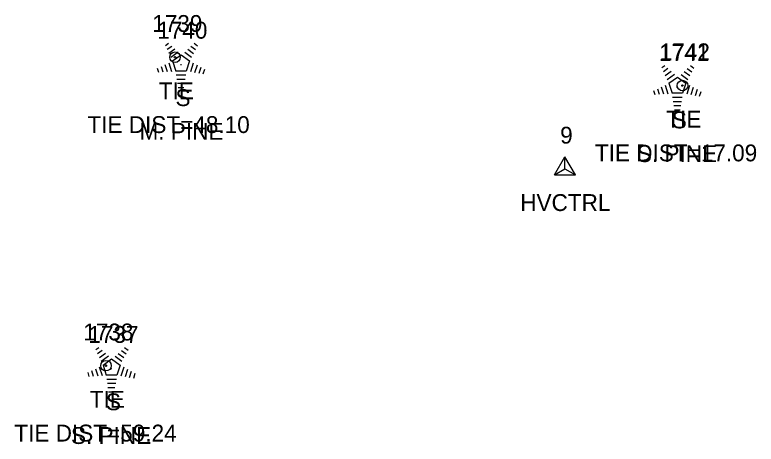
# Model space of a CAD drawing. Extents: x 1654425 to 1656893, y 667839 to 678429.
# Drawn here: x 1654809.7 to 1654897.6, y 669185.3 to 669236.3 of the extents above; entities that cross this region are included whole.
import ezdxf

# ---------------------------------------------------------------- set-up
doc = ezdxf.new("R2010")
doc.units = 0
for name, color, linetype in [('C_A', 7, 'Continuous'), ('C_C', 7, 'Continuous'), ('C_I', 7, 'Continuous'), ('CBP', 7, 'Continuous'), ('CPSM', 7, 'Continuous'), ('L_A', 7, 'Continuous'), ('L_C', 7, 'Continuous'), ('L_I', 7, 'Continuous'), ('LTC', 7, 'Continuous')]:
    doc.layers.add(name, color=color, linetype=linetype)

msp = doc.modelspace()

# ---------------------------------------------------------------- linework, layer by layer
at = {"layer": 'CBP'}
for centre, radius in [((1654828.731, 669231.26), 0.625), ((1654828.731, 669231.26), 0.0833), ((1654888.911, 669227.898), 0.625), ((1654888.911, 669227.898), 0.0833), ((1654820.541, 669194.645), 0.625), ((1654820.541, 669194.645), 0.0833)]:
    msp.add_circle(centre, radius, dxfattribs=at)
at = {"layer": 'CPSM'}
for p, q in [((1654873.728, 669217.283), (1654874.978, 669219.448)), ((1654876.228, 669217.283), (1654874.978, 669219.448)), ((1654874.978, 669218.004), (1654874.978, 669219.448)), ((1654873.728, 669217.283), (1654874.978, 669218.004)), ((1654874.978, 669218.004), (1654874.978, 669218.004)), ((1654874.978, 669218.004), (1654876.228, 669217.283)), ((1654873.728, 669217.283), (1654876.228, 669217.283))]:
    msp.add_line(p, q, dxfattribs=at)
at = {"layer": 'LTC'}
for p, q in [((1654827.597, 669232.666), (1654827.952, 669232.923)), ((1654830.995, 669232.906), (1654831.414, 669232.602)), ((1654827.807, 669232.201), (1654828.336, 669232.585)), ((1654828.016, 669231.735), (1654828.72, 669232.246)), ((1654830.253, 669232.21), (1654830.932, 669231.716)), ((1654830.624, 669232.558), (1654831.174, 669232.159)), ((1654828.226, 669231.269), (1654829.104, 669231.907)), ((1654828.45, 669230.814), (1654829.462, 669231.548)), ((1654829.462, 669231.548), (1654830.459, 669230.823)), ((1654829.882, 669231.861), (1654830.692, 669231.273)), ((1654827.54, 669230.378), (1654827.812, 669229.543)), ((1654827.996, 669230.595), (1654828.327, 669229.576)), ((1654828.45, 669230.814), (1654828.837, 669229.621)), ((1654830.459, 669230.823), (1654830.068, 669229.621)), ((1654830.897, 669230.553), (1654830.559, 669229.513)), ((1654831.341, 669230.302), (1654831.054, 669229.418)), ((1654886.451, 669230.021), (1654886.806, 669230.278)), ((1654889.849, 669230.261), (1654890.268, 669229.957)), ((1654826.629, 669229.945), (1654826.782, 669229.477)), ((1654827.085, 669230.162), (1654827.297, 669229.51)), ((1654830.068, 669229.621), (1654828.837, 669229.621)), ((1654831.786, 669230.052), (1654831.549, 669229.323)), ((1654832.23, 669229.802), (1654832.043, 669229.228)), ((1654886.661, 669229.555), (1654887.19, 669229.94)), ((1654886.87, 669229.09), (1654887.574, 669229.601)), ((1654889.107, 669229.565), (1654889.786, 669229.071)), ((1654889.478, 669229.913), (1654890.028, 669229.514)), ((1654830.029, 669229.121), (1654828.885, 669229.121)), ((1654829.946, 669228.621), (1654828.957, 669228.621)), ((1654887.08, 669228.624), (1654887.958, 669229.262)), ((1654887.304, 669228.169), (1654888.316, 669228.903)), ((1654888.316, 669228.903), (1654889.313, 669228.178)), ((1654888.736, 669229.216), (1654889.546, 669228.628)), ((1654829.862, 669228.121), (1654829.03, 669228.121)), ((1654829.778, 669227.621), (1654829.103, 669227.621)), ((1654886.394, 669227.733), (1654886.666, 669226.898)), ((1654886.85, 669227.95), (1654887.181, 669226.93)), ((1654887.304, 669228.169), (1654887.691, 669226.975)), ((1654889.313, 669228.178), (1654888.922, 669226.975)), ((1654889.751, 669227.908), (1654889.413, 669226.868)), ((1654890.195, 669227.657), (1654889.908, 669226.773)), ((1654885.483, 669227.3), (1654885.636, 669226.832)), ((1654885.939, 669227.517), (1654886.151, 669226.865)), ((1654888.922, 669226.975), (1654887.691, 669226.975)), ((1654890.64, 669227.407), (1654890.403, 669226.678)), ((1654891.084, 669227.157), (1654890.897, 669226.583)), ((1654888.883, 669226.475), (1654887.739, 669226.475)), ((1654888.8, 669225.975), (1654887.811, 669225.975)), ((1654888.716, 669225.475), (1654887.884, 669225.475)), ((1654888.632, 669224.975), (1654887.957, 669224.975)), ((1654819.346, 669196.564), (1654819.7, 669196.822)), ((1654822.744, 669196.805), (1654823.163, 669196.5)), ((1654819.555, 669196.099), (1654820.085, 669196.483)), ((1654819.765, 669195.633), (1654820.469, 669196.144)), ((1654822.002, 669196.108), (1654822.681, 669195.614)), ((1654822.373, 669196.456), (1654822.923, 669196.057)), ((1654819.975, 669195.167), (1654820.853, 669195.805)), ((1654820.199, 669194.712), (1654821.211, 669195.447)), ((1654821.211, 669195.447), (1654822.208, 669194.722)), ((1654821.631, 669195.76), (1654822.44, 669195.171)), ((1654819.289, 669194.277), (1654819.56, 669193.441)), ((1654819.745, 669194.493), (1654820.075, 669193.474)), ((1654820.199, 669194.712), (1654820.586, 669193.519)), ((1654822.208, 669194.722), (1654821.817, 669193.519)), ((1654822.645, 669194.451), (1654822.308, 669193.411)), ((1654823.09, 669194.2), (1654822.803, 669193.316)), ((1654818.378, 669193.843), (1654818.53, 669193.375)), ((1654818.834, 669194.06), (1654819.045, 669193.408)), ((1654821.817, 669193.519), (1654820.586, 669193.519)), ((1654823.535, 669193.95), (1654823.298, 669193.221)), ((1654823.979, 669193.7), (1654823.792, 669193.126)), ((1654821.778, 669193.019), (1654820.634, 669193.019)), ((1654821.695, 669192.519), (1654820.706, 669192.519)), ((1654821.611, 669192.019), (1654820.779, 669192.019)), ((1654821.527, 669191.519), (1654820.852, 669191.519))]:
    msp.add_line(p, q, dxfattribs=at)

# ---------------------------------------------------------------- texts
at = {"layer": 'C_A'}
for s, p in [('TIE', (1654826.81, 669226.26)), ('TIE', (1654886.99, 669222.898)), ('HVCTRL', (1654869.671, 669213.004)), ('TIE', (1654818.62, 669189.645))]:
    msp.add_text(s, height=2, dxfattribs=at).set_placement(p)
at = {"layer": 'C_C'}
for s, p in [('TIE DIST=48.10', (1654818.345, 669222.26)), ('TIE DIST=17.09', (1654878.526, 669218.898)), ('TIE DIST=59.24', (1654809.676, 669185.645))]:
    msp.add_text(s, height=2, dxfattribs=at).set_placement(p)
at = {"layer": 'C_I'}
for s, p in [('1739', (1654826.03, 669234.26)), ('1742', (1654886.218, 669230.898)), ('9', (1654874.403, 669221.004)), ('1738', (1654817.849, 669197.645))]:
    msp.add_text(s, height=2, dxfattribs=at).set_placement(p)
at = {"layer": 'L_A'}
for p in [(1654828.788, 669225.458), (1654887.642, 669222.813), (1654820.537, 669189.356)]:
    msp.add_text('S', height=2, dxfattribs=at).set_placement(p)
at = {"layer": 'L_C'}
for s, p in [('M. PINE', (1654824.52, 669221.458)), ('S. PINE', (1654883.5, 669218.813)), ('S. PINE', (1654816.395, 669185.356))]:
    msp.add_text(s, height=2, dxfattribs=at).set_placement(p)
at = {"layer": 'L_I'}
for s, p in [('1740', (1654826.622, 669233.458)), ('1741', (1654886.13, 669230.813)), ('1737', (1654818.458, 669197.356))]:
    msp.add_text(s, height=2, dxfattribs=at).set_placement(p)
at = {"layer": 'LTC'}
for p in [(1654829.344, 669230.562), (1654888.198, 669227.917), (1654821.093, 669194.46)]:
    msp.add_text('.', height=1.037, rotation=270, dxfattribs=at).set_placement(p)

doc.saveas('drawing.dxf')
